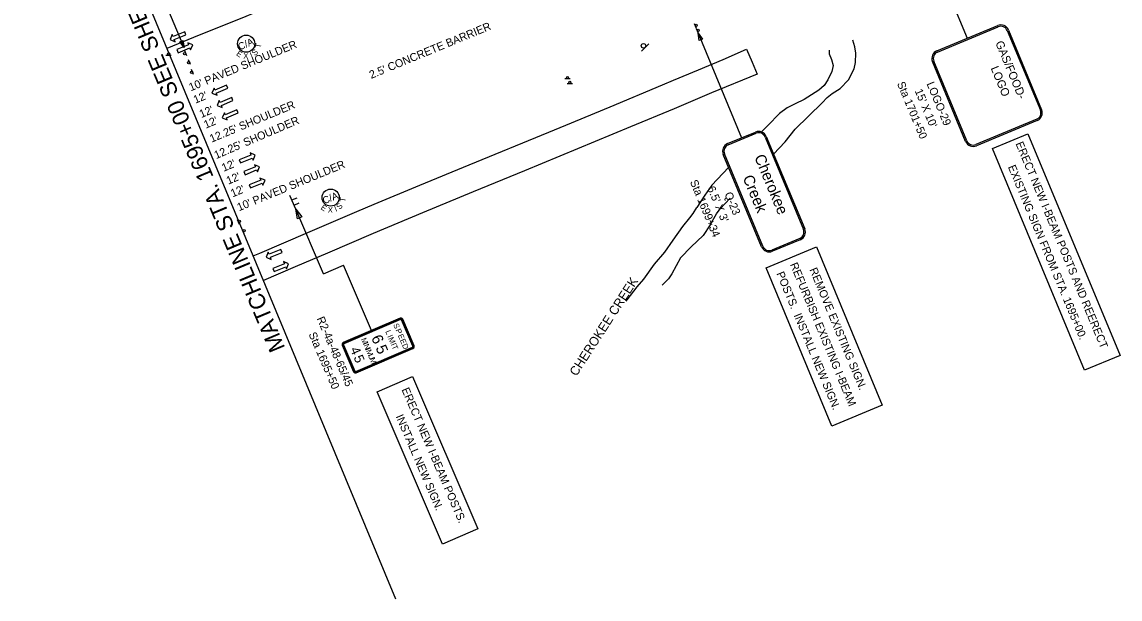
# Model space of a CAD drawing. Extents: x 1816080 to 1817753, y 1191002 to 1192408.
# Drawn here: x 1816080 to 1817041, y 1191002 to 1191507 of the extents above; entities that cross this region are included whole.
import ezdxf

# ---------------------------------------------------------------- set-up
doc = ezdxf.new("R2010")
doc.units = 0
for name, color, linetype in [('RD_EX_H2O', 7, 'Continuous'), ('RD_EX_Road', 7, 'Continuous'), ('RD_PD_Final_LnLine', 7, 'Continuous'), ('RD_PD_Final_TX', 7, 'Continuous'), ('RD_SHT_MatchLine', 7, 'Continuous'), ('RD_SHT_TX', 7, 'Continuous'), ('RD_Sketch8', 7, 'Continuous'), ('RD_TX_RoadID', 7, 'Continuous'), ('SN_P_Signs', 7, 'Continuous')]:
    doc.layers.add(name, color=color, linetype=linetype)

# ---------------------------------------------------------------- blocks, each defined once
blk = doc.blocks.new('SARRW2')
at = {"layer": 'RD_PD_Final_LnLine'}
blk.add_lwpolyline([(-12, 1.2), (-12, -1.2), (-2.83, -1.2), (-2.83, -2.83), (0, 0), (-2.83, 2.83), (-2.83, 1.2)], close=True, dxfattribs=at)

msp = doc.modelspace()

# ---------------------------------------------------------------- linework, layer by layer
at = {"layer": 'RD_EX_H2O'}
for points in [[(1816780.19, 1191436.57), (1816784.59, 1191441.4), (1816788.93, 1191444.67), (1816796, 1191449.06), (1816803.2, 1191456.87), (1816808.14, 1191466.29), (1816809.42, 1191471.79), (1816809.71, 1191480.13), (1816808.76, 1191485.59), (1816807.13, 1191491.57)], [(1816786.29, 1191482.84), (1816786.24, 1191479.46), (1816788.26, 1191474.43), (1816789.86, 1191469.23), (1816788.76, 1191464.16), (1816785.09, 1191456.68), (1816781.94, 1191451.83), (1816777.24, 1191447.71), (1816764.39, 1191439.64), (1816756.64, 1191435.86), (1816749.69, 1191432.29), (1816742.91, 1191427.31), (1816732.64, 1191416.69), (1816727.09, 1191411.19)], [(1816737.78, 1191391.69), (1816747.72, 1191402.49), (1816756.66, 1191413.58), (1816780.19, 1191436.57)], [(1816698.42, 1191379.9), (1816683.71, 1191364.47), (1816677.44, 1191355.9), (1816670.63, 1191345.05)], [(1816682.38, 1191329.96), (1816687.83, 1191339.5), (1816691.02, 1191343.84), (1816699.64, 1191353.06)], [(1816608.61, 1191263.06), (1816609.58, 1191264.24), (1816618.45, 1191275.64), (1816624.26, 1191282.2), (1816633.58, 1191295.47), (1816642.6, 1191305.8), (1816649.91, 1191316.33), (1816658.35, 1191328.53), (1816664.32, 1191335.88), (1816667.51, 1191339.88), (1816670.63, 1191345.05)], [(1816682.38, 1191329.96), (1816676.12, 1191320.51), (1816665.6, 1191310.48), (1816656.34, 1191300.89), (1816652.62, 1191293.92), (1816648.75, 1191286.88), (1816645.89, 1191282.54), (1816640.26, 1191277.09)]]:
    msp.add_lwpolyline(points, dxfattribs=at)
at = {"layer": 'RD_EX_Road'}
for points in [[(1816550.6, 1191626.95), (1816559.95, 1191622.95), (1816529.85, 1191610.9), (1816525.09, 1191609.33), (1816516.83, 1191607.04), (1816501.56, 1191602.44), (1816492, 1191599.57), (1816481.01, 1191595.11), (1816437.42, 1191576.88), (1816390.61, 1191557.7), (1816355.1, 1191542.99), (1816335.12, 1191535.64), (1816319.86, 1191529.84), (1816310.03, 1191526.5), (1816272.57, 1191510.76), (1816235.07, 1191495.79), (1816207.01, 1191484.27)], [(1816282.48, 1191302.66), (1816288.21, 1191305.19), (1816330.18, 1191323.23), (1816373.02, 1191341.62), (1816388.2, 1191348.03), (1816428.27, 1191364.47), (1816471.49, 1191382.31), (1816541.11, 1191410.96), (1816555.91, 1191417), (1816594.78, 1191433.14), (1816640.66, 1191452.36), (1816650.19, 1191456.34), (1816672.02, 1191465.5), (1816693.54, 1191474.53), (1816714.09, 1191483.45), (1816718.85, 1191472.31), (1816723.32, 1191461.76), (1816683.29, 1191445.3), (1816650.6, 1191431.5), (1816612.59, 1191415.53), (1816566.08, 1191396.3), (1816519.67, 1191377.22), (1816474.93, 1191358.64), (1816430.44, 1191340.28), (1816387.53, 1191322.39), (1816347.37, 1191305.06), (1816319.05, 1191293.01), (1816291.4, 1191281.2)]]:
    msp.add_lwpolyline(points, dxfattribs=at)
at = {"layer": 'RD_SHT_MatchLine'}
msp.add_line((1816407.28, 1191002.35), (1816080.19, 1191789.44), dxfattribs=at)
at = {"layer": 'RD_Sketch8'}
for centre in [(1816276.33, 1191488.36), (1816350.25, 1191353.69)]:
    msp.add_circle(centre, 7.5, dxfattribs=at)
at = {"layer": 'SN_P_Signs'}
for p, q in [((1816873.82, 1191573.49), (1816907.2, 1191493.18)), ((1816221.98, 1191484.99), (1816204.66, 1191526.69)), ((1816668.21, 1191506.03), (1816669.94, 1191501.87)), ((1816669.93, 1191501.71), (1816671.66, 1191497.56)), ((1816671.66, 1191497.56), (1816709.72, 1191405.97)), ((1816622.11, 1191481.92), (1816628.48, 1191488.29)), ((1816206.17, 1191478.37), (1816210.67, 1191478.37)), ((1816224.3, 1191477.84), (1816222.6, 1191482)), ((1816227.71, 1191470.08), (1816226.01, 1191474.25)), ((1816230.33, 1191461.54), (1816228.62, 1191465.71)), ((1816555.19, 1191457.79), (1816559.69, 1191457.79)), ((1816557.24, 1191453.61), (1816561.74, 1191453.61)), ((1816731.35, 1191407.16), (1816764.97, 1191326.27)), ((1816929.16, 1191396.54), (1816960.2, 1191409.44)), ((1816960.2, 1191409.44), (1817040.8, 1191215.5)), ((1817009.76, 1191202.6), (1816929.16, 1191396.54)), ((1816319.76, 1191343.45), (1816314.61, 1191355.43)), ((1816316.23, 1191351.65), (1816320.82, 1191353.62)), ((1816318.21, 1191347.04), (1816322.8, 1191349.01)), ((1816344.03, 1191286.96), (1816319.76, 1191343.45)), ((1816268.52, 1191334.55), (1816270.25, 1191330.4)), ((1816272.67, 1191326.33), (1816274.39, 1191322.17)), ((1816731.22, 1191292.18), (1816775.19, 1191310.45)), ((1816775.19, 1191310.45), (1816832.77, 1191171.92)), ((1816344.03, 1191286.96), (1816361.59, 1191294.51)), ((1816386.09, 1191237.48), (1816361.59, 1191294.51)), ((1816788.79, 1191153.65), (1816731.22, 1191292.18)), ((1816410.9, 1191248.14), (1816361.28, 1191226.82)), ((1816423.21, 1191224.04), (1816413.26, 1191247.19)), ((1816360.34, 1191224.46), (1816370.29, 1191201.3)), ((1816372.65, 1191200.36), (1816422.27, 1191221.68)), ((1817040.8, 1191215.5), (1817009.76, 1191202.6)), ((1816390.9, 1191183.7), (1816421.79, 1191196.97)), ((1816421.79, 1191196.97), (1816479.04, 1191063.73)), ((1816448.15, 1191050.46), (1816390.9, 1191183.7)), ((1816832.77, 1191171.92), (1816788.79, 1191153.65)), ((1816479.04, 1191063.73), (1816448.15, 1191050.46))]:
    msp.add_line(p, q, dxfattribs=at)
for points in [[(1816672.6, 1191491.29), (1816671.66, 1191497.56), (1816675.44, 1191492.47)], [(1816221.04, 1191491.26), (1816221.98, 1191484.99), (1816218.2, 1191490.08)], [(1816321.11, 1191335.11), (1816319.76, 1191343.45), (1816324.88, 1191336.73)]]:
    msp.add_lwpolyline(points, close=True, dxfattribs=at)
for points in [[(1816880.6, 1191482.13), (1816933.79, 1191504.23)], [(1816881.06, 1191481.02), (1816934.25, 1191503.12)], [(1816942.1, 1191499.88), (1816971.11, 1191430.07)], [(1816943.21, 1191500.35), (1816972.22, 1191430.53)], [(1816905.73, 1191402.9), (1816876.72, 1191472.71)], [(1816906.84, 1191403.36), (1816877.83, 1191473.18)], [(1816967.87, 1191422.23), (1816914.68, 1191400.13)], [(1816968.33, 1191421.12), (1816915.14, 1191399.02)], [(1816697.5, 1191400.89), (1816721.94, 1191411.05)], [(1816697.96, 1191399.78), (1816722.4, 1191409.94)], [(1816730.25, 1191406.7), (1816763.86, 1191325.81)], [(1816727.23, 1191310.58), (1816693.61, 1191391.48)], [(1816728.34, 1191311.04), (1816694.72, 1191391.94)], [(1816760.62, 1191317.96), (1816736.18, 1191307.8)], [(1816761.09, 1191316.86), (1816736.64, 1191306.7)], [(1816411.08, 1191247.72), (1816361.46, 1191226.41)], [(1816411.37, 1191247.04), (1816361.76, 1191225.72)], [(1816422.11, 1191223.57), (1816412.16, 1191246.72)], [(1816422.8, 1191223.86), (1816412.85, 1191247.02)], [(1816360.75, 1191224.63), (1816370.7, 1191201.48)], [(1816361.44, 1191224.93), (1816371.39, 1191201.78)], [(1816372.18, 1191201.46), (1816421.79, 1191222.78)], [(1816372.48, 1191200.77), (1816422.09, 1191222.09)]]:
    msp.add_lwpolyline(points, dxfattribs=at)
for centre, radius in [((1816670.01, 1191504.33), 1), ((1816671.73, 1191500.02), 1), ((1816623.88, 1191486.55), 2), ((1816208.43, 1191479.38), 1), ((1816222.51, 1191479.54), 1), ((1816225.92, 1191471.79), 1), ((1816228.54, 1191463.25), 1), ((1816557.44, 1191458.8), 1), ((1816559.49, 1191454.62), 1), ((1816270.33, 1191332.86), 1), ((1816274.47, 1191324.63), 1)]:
    msp.add_circle(centre, radius, dxfattribs=at)
for centre, radius, start, end in [((1816936.56, 1191497.58), 7.2, 22.56659, 112.56659), ((1816936.56, 1191497.58), 6, 22.56659, 112.56659), ((1816883.37, 1191475.48), 7.2, 112.56659, 202.56659), ((1816883.37, 1191475.48), 6, 112.56659, 202.56659), ((1816965.57, 1191427.77), 6, 292.56659, 22.56659), ((1816965.57, 1191427.77), 7.2, 292.56659, 22.56659), ((1816724.71, 1191404.4), 7.2, 22.56659, 112.56659), ((1816724.71, 1191404.4), 6, 22.56659, 112.56659), ((1816912.38, 1191405.67), 7.2, 202.56659, 292.56659), ((1816912.38, 1191405.67), 6, 202.56659, 292.56659), ((1816700.26, 1191394.24), 7.2, 112.56659, 202.56659), ((1816700.26, 1191394.24), 6, 112.56659, 202.56659), ((1816758.32, 1191323.5), 6, 292.56659, 22.56659), ((1816758.32, 1191323.5), 7.2, 292.56659, 22.56659), ((1816733.88, 1191313.35), 7.2, 202.56659, 292.56659), ((1816733.88, 1191313.35), 6, 202.56659, 292.56659), ((1816411.61, 1191246.48), 1.8, 23.25009, 113.25009), ((1816411.61, 1191246.48), 1.35, 23.25009, 113.25009), ((1816411.61, 1191246.48), 0.6, 23.25009, 113.25009), ((1816362, 1191225.17), 1.8, 113.25009, 203.25009), ((1816362, 1191225.17), 1.35, 113.25009, 203.25009), ((1816362, 1191225.17), 0.6, 113.25009, 203.25009), ((1816421.56, 1191223.33), 0.6, 293.25009, 23.25009), ((1816421.56, 1191223.33), 1.35, 293.25009, 23.25009), ((1816421.56, 1191223.33), 1.8, 293.25009, 23.25009), ((1816371.94, 1191202.01), 1.8, 203.25009, 293.25009), ((1816371.94, 1191202.01), 1.35, 203.25009, 293.25009), ((1816371.94, 1191202.01), 0.6, 203.25009, 293.25009)]:
    msp.add_arc(centre, radius, start, end, dxfattribs=at)

# ---------------------------------------------------------------- block references
at = {"layer": 'RD_PD_Final_LnLine', "xscale": 1.2000000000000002}
for p, yscale, rotation in [((1816209.78, 1191491.93), 1.2000000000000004, -157.44760385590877), ((1816229.59, 1191487.36), 1.2000000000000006, 22.552396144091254), ((1816246.43, 1191445.13), 1.2000000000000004, -157.44760385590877), ((1816250.91, 1191434.34), 1.2000000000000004, -157.44760385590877), ((1816255.4, 1191423.55), 1.2000000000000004, -157.44760385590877), ((1816284.15, 1191390.89), 1.2000000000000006, 22.552396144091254), ((1816288.09, 1191380.58), 1.2000000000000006, 22.552396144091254), ((1816292.82, 1191368.94), 1.2000000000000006, 22.552396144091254), ((1816293.88, 1191301.44), 1.2000000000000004, -157.44760385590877), ((1816313.49, 1191295.82), 1.2000000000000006, 22.552396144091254)]:
    msp.add_blockref('SARRW2', p, dxfattribs=dict(at, yscale=yscale, rotation=rotation))

# ---------------------------------------------------------------- texts
at = {"layer": 'RD_PD_Final_TX'}
for s, rotation, p in [("2.5' CONCRETE BARRIER", 22.4268, (1816385.73, 1191457.53)), ("10' PAVED SHOULDER", 22.4268, (1816227.9, 1191446.65)), ("12'", 22.75903, (1816231.88, 1191435.79)), ("12'", 22.75903, (1816237.09, 1191423.25)), ("12.25' SHOULDER", 22.56659, (1816246.09, 1191401.72)), ("12'", 22.75903, (1816240.97, 1191413.92)), ("12.25' SHOULDER", 23.24055, (1816250.09, 1191387.29)), ("12'", 22.75903, (1816256.64, 1191376.2)), ("10' PAVED SHOULDER", 22.4268, (1816270.07, 1191341.68)), ("12'", 22.75903, (1816260.7, 1191364.95)), ("12'", 22.75903, (1816264.5, 1191353.84))]:
    msp.add_text(s, height=7, rotation=rotation, dxfattribs=at).set_placement(p)
at = {"layer": 'RD_SHT_TX'}
msp.add_text('MATCHLINE STA. 1695+00 SEE SHEET NO. SN56', height=14.1726, rotation=112.67894, dxfattribs=at).set_placement((1816310.65, 1191222.14))
at = {"layer": 'RD_Sketch8'}
for s, height, rotation, p in [('C/A', 6.25, 22.56659, (1816270.74, 1191482.49)), ('T', 5, 80.75173, (1816289.08, 1191484.23)), ('E', 5, 325.77783, (1816267.16, 1191478.57)), ('X', 5, 358.2072, (1816273.75, 1191475.19)), ('I', 5, 22.3672, (1816280.81, 1191475.88)), ('S', 5, 44.35903, (1816284.11, 1191477.44)), ('C/A', 6.25, 22.56659, (1816344.66, 1191347.82)), ('T', 5, 80.75173, (1816363, 1191349.56)), ('E', 5, 325.77783, (1816341.08, 1191343.9)), ('X', 5, 358.2072, (1816347.67, 1191340.51)), ('I', 5, 22.3672, (1816354.73, 1191341.2)), ('S', 5, 44.35903, (1816358.03, 1191342.76))]:
    msp.add_text(s, height=height, rotation=rotation, dxfattribs=at).set_placement(p)
at = {"layer": 'RD_TX_RoadID'}
msp.add_text('CHEROKEE CREEK', height=8, rotation=57.17201, dxfattribs=at).set_placement((1816565.34, 1191196.8))
at = {"layer": 'SN_P_Signs'}
for s, height, rotation, p in [('GAS/FOOD-', 7.2, 292.56659, (1816931.56, 1191489.1)), ('LOGO', 7.2, 292.56659, (1816927.49, 1191466.99)), ('Sta 1701+50', 7, 292.56667, (1816845.53, 1191453.51)), ('LOGO-29', 7, 292.56667, (1816871.38, 1191453.33)), ("15' X 10'", 7, 292.56667, (1816861.04, 1191447.18)), ('ERECT NEW I-BEAM POSTS AND REERECT', 6.9998, 292.56667, (1816949.27, 1191400.93)), ('Cherokee', 9.6, 292.56659, (1816720.68, 1191389.2)), ('EXISTING SIGN FROM STA. 1695+00.', 6.9998, 292.56667, (1816942.57, 1191380.57)), ('Creek', 9.6, 292.56659, (1816710.52, 1191371.12)), ('Sta 1699+34', 7, 292.56667, (1816664.37, 1191367.58)), ("6.5' X 3'", 7, 292.56667, (1816679.57, 1191362.02)), ('Q-23', 7, 292.56667, (1816694.6, 1191356.87)), ('REFURBISH EXISTING I-BEAM', 6.9998, 292.56667, (1816751.92, 1191295.17)), ('POSTS.  INSTALL NEW SIGN.', 6.9998, 292.56667, (1816740.05, 1191287.23)), ('REMOVE EXISTING SIGN.', 6.9998, 292.56667, (1816768.93, 1191290.7)), ('R2-4a-48-65/45', 7, 293.25017, (1816337.87, 1191247.82)), ('L', 4.8, 293.25009, (1816397.95, 1191236.47)), ('S', 4.8, 293.25009, (1816404.86, 1191242.45)), ('P', 4.8, 293.25009, (1816406.87, 1191237.76)), ('Sta 1695+50', 7, 293.25017, (1816330.77, 1191234.21)), ('M', 4.8, 293.25009, (1816376.68, 1191229.74)), ('6', 9.6, 293.25009, (1816385.55, 1191231.14)), ('I', 4.8, 293.25009, (1816399.74, 1191232.32)), ('M', 4.8, 293.25009, (1816400.55, 1191230.43)), ('E', 4.8, 293.25009, (1816408.88, 1191233.07)), ('E', 4.8, 293.25009, (1816410.68, 1191228.9)), ('4', 8.4, 293.25009, (1816367.08, 1191220.93)), ('I', 4.8, 293.25009, (1816378.31, 1191225.95)), ('N', 4.8, 293.25009, (1816378.98, 1191224.4)), ('I', 4.8, 293.25009, (1816380.41, 1191221.06)), ('M', 4.8, 293.25009, (1816381.08, 1191219.51)), ('5', 9.6, 293.25009, (1816389.35, 1191222.29)), ('I', 4.8, 293.25009, (1816402.79, 1191225.22)), ('T', 4.8, 293.25009, (1816403.5, 1191223.56)), ('D', 4.8, 293.25009, (1816412.47, 1191224.72)), ('5', 8.4, 293.25009, (1816370.14, 1191213.81)), ('U', 4.8, 293.25009, (1816382.71, 1191215.72)), ('M', 4.8, 293.25009, (1816384.14, 1191212.38)), ('ERECT NEW I-BEAM POSTS.', 6.9998, 293.25017, (1816412.1, 1191185.68)), ('INSTALL NEW SIGN.', 6.9998, 293.25017, (1816406.96, 1191162.18))]:
    msp.add_text(s, height=height, rotation=rotation, dxfattribs=at).set_placement(p)

doc.saveas('drawing.dxf')
